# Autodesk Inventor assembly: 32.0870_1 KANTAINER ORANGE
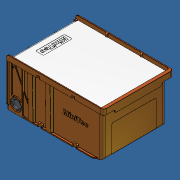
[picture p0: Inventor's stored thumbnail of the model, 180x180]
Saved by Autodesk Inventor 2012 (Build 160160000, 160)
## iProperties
Created: 2013-07
Part Number: 32.0870_1 KANTAINER ORANGE
Document SubType Name: Assembly
Designer: Admin
Author: Admin
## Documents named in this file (5)
- C:\Andys Backup Data\ANDY'S INVENTOR\INVENTOR LIBRARIES\PARTS LIBRARY\KANBAN SYSTEMS\32.0870_1 KANTAINER ORANGE.iam
- C:\Andys Backup Data\ANDY'S INVENTOR\INVENTOR LIBRARIES\PARTS LIBRARY\KANBAN SYSTEMS\SUBCOMPONENTS\32.0870_1 KANTAINER DIVIDER.ipt
- C:\Andys Backup Data\ANDY'S INVENTOR\INVENTOR LIBRARIES\PARTS LIBRARY\KANBAN SYSTEMS\SUBCOMPONENTS\32.0870_1 KANTAINER FOLD OUT TRAY.ipt
- C:\Andys Backup Data\ANDY'S INVENTOR\INVENTOR LIBRARIES\PARTS LIBRARY\KANBAN SYSTEMS\SUBCOMPONENTS\32.0870_1 KANTAINER LID.ipt
- C:\Andys Backup Data\ANDY'S INVENTOR\INVENTOR LIBRARIES\PARTS LIBRARY\KANBAN SYSTEMS\SUBCOMPONENTS\32.0870_1 KANTAINER ORANGE.ipt
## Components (4 placed, 4 different names)
1. 32.0870_1 KANTAINER ORANGE:1 — Mate:2, Mate:3, Mate:4, Mate:5, Flush:1, Angle:1, Mate:6, Mate:7, Mate:8
2. 32.0870_1 KANTAINER DIVIDER:1 — Mate:2, Mate:3, Mate:4
3. 32.0870_1 KANTAINER FOLD OUT TRAY:1 — Mate:5, Flush:1, Angle:1
4. 32.0870_1 KANTAINER LID:1 — Mate:6, Mate:7, Mate:8
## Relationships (9: Mate 7, Flush 1, Angle 1)
- Mate:2: 32.0870_1 KANTAINER ORANGE:1 ↔ 32.0870_1 KANTAINER DIVIDER:1
- Mate:3: 32.0870_1 KANTAINER ORANGE:1 ↔ 32.0870_1 KANTAINER DIVIDER:1
- Mate:4: 32.0870_1 KANTAINER ORANGE:1 ↔ 32.0870_1 KANTAINER DIVIDER:1
- Mate:5: 32.0870_1 KANTAINER ORANGE:1 ↔ 32.0870_1 KANTAINER FOLD OUT TRAY:1
- Flush:1: 32.0870_1 KANTAINER ORANGE:1 ↔ 32.0870_1 KANTAINER FOLD OUT TRAY:1
- Angle:1: 32.0870_1 KANTAINER ORANGE:1 ↔ 32.0870_1 KANTAINER FOLD OUT TRAY:1
- Mate:6: 32.0870_1 KANTAINER ORANGE:1 ↔ 32.0870_1 KANTAINER LID:1
- Mate:7: 32.0870_1 KANTAINER ORANGE:1 ↔ 32.0870_1 KANTAINER LID:1
- Mate:8: 32.0870_1 KANTAINER ORANGE:1 ↔ 32.0870_1 KANTAINER LID:1
